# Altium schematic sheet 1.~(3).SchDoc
size 420 x 297 mm
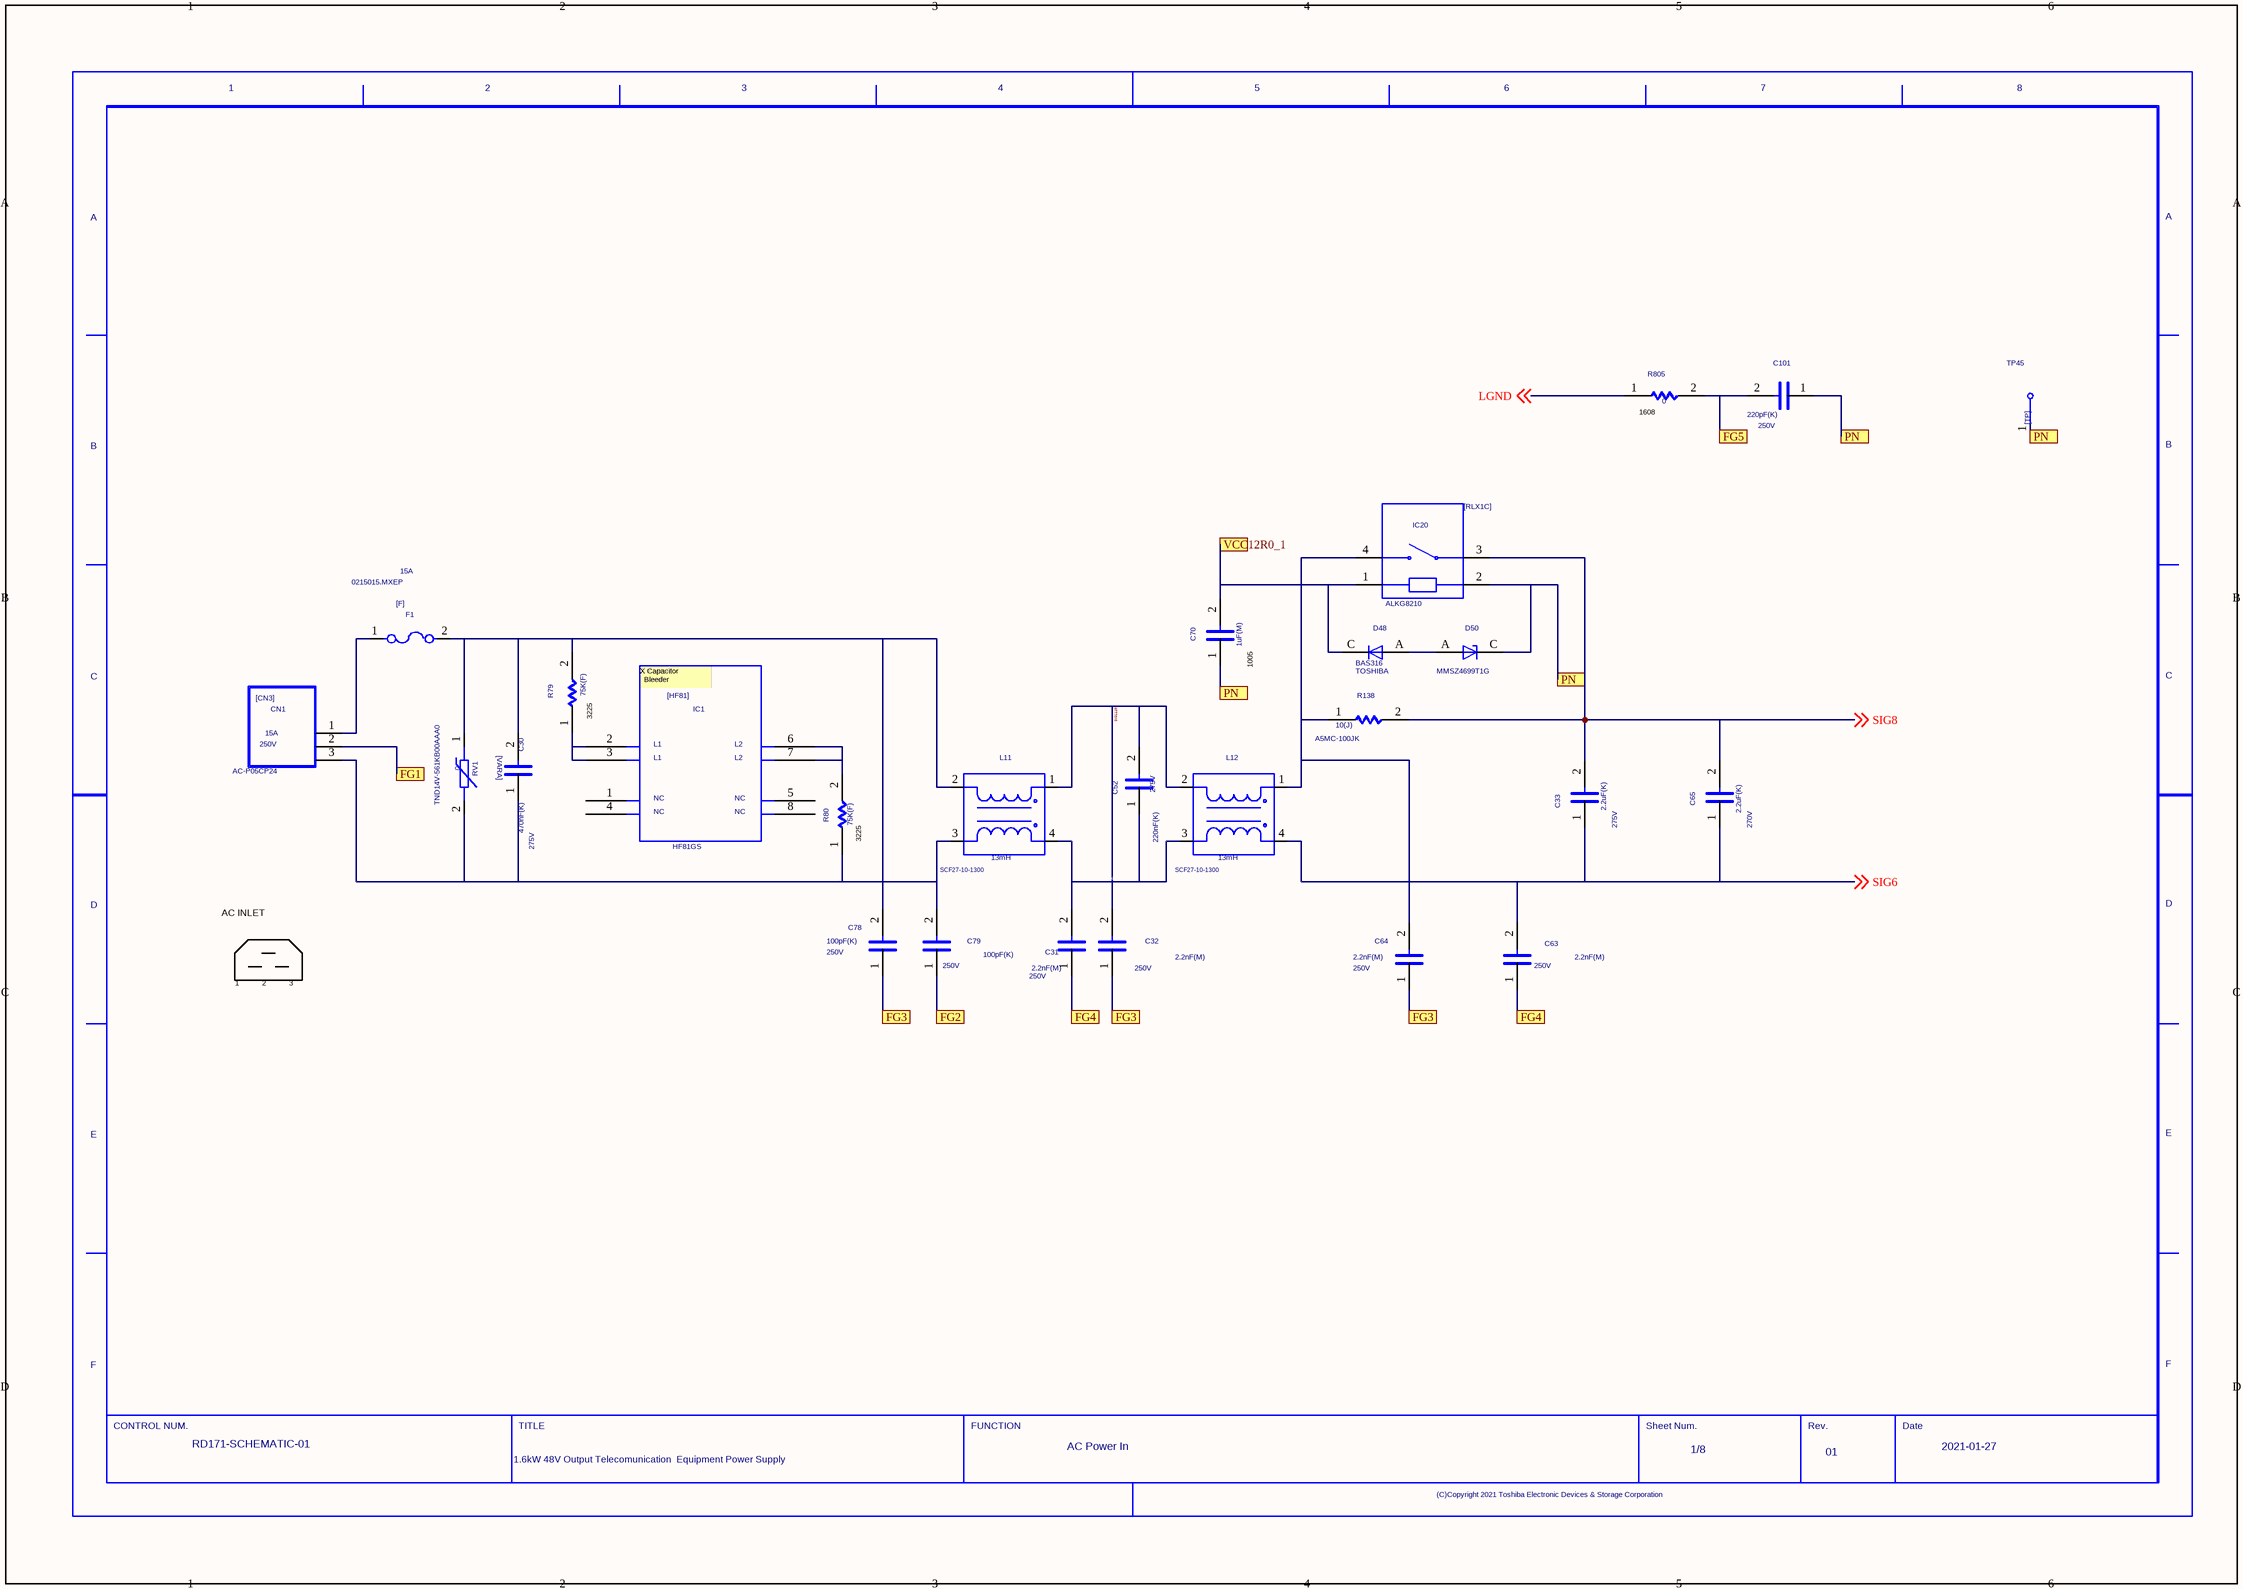
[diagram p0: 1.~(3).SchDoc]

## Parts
C30  VAL2: 275V  VAL1: 470nF(K)  [LE474-M]  (hidden comment: 470nF)
C31  VAL2: 250V  VAL1: 2.2nF(M)  [DE2E3KY222MN3AM02F]  (hidden comment: 2.2nF)
C32  VAL2: 250V  VAL1: 2.2nF(M)  [DE2E3KY222MN3AM02F]  (hidden comment: 2.2nF)
C33  VAL2: 275V  VAL1: 2.2uF(K)  [890324026034CS]  (hidden comment: 2.2uF)
C52  VAL2: 275V  VAL1: 220nF(K)  [LE224-M]  (hidden comment: 220nF)
C63  VAL2: 250V  VAL1: 2.2nF(M)  [DE2E3KY222MN3AM02F]  (hidden comment: 2.2nF)
C64  VAL2: 250V  VAL1: 2.2nF(M)  [DE2E3KY222MN3AM02F]  (hidden comment: 2.2nF)
C65  VAL2: 270V  VAL1: 2.2uF(K)  [890324026034CS]  (hidden comment: 2.2uF)
C70  VAL1: 1uF(M)  (hidden comment: 1uF)
C78  VAL2: 250V  VAL1: 100pF(K)  [DE2B3KY101KA3BM02F]  (hidden comment: 100pF)
C79  VAL2: 250V  VAL1: 100pF(K)  [DE2B3KY101KA3BM02F]  (hidden comment: 100pF)
C101  VAL2: 250V  VAL1: 220pF(K)  [DE2B3KY221KA3BM02F]  (hidden comment: 220pF)
CN1  VAL2: 250V  [AC-P05CP24]  (hidden comment: 15A)
D48  USERCOMPTEXT3: TOSHIBA  [BAS316]  (hidden comment: D48)
D50  D50  [MMSZ4699T1G]  (value not drawn)
F1  VAL1: 15A  [0215015.MXEP]  (hidden comment: 15 A)
IC1  IC1  [HF81GS]  (value not drawn)
IC20  IC20  [ALKG8210]  (value not drawn)
L11  13mH  [SCF27-10-1300]
L12  13mH  [SCF27-10-1300]
R79  VAL1: 75K(F)  (hidden comment: 75k)
R80  VAL1: 75K(F)  (hidden comment: 75k)
R138  VAL1: 10(J)  [A5MC-100JK]  (hidden comment: 10_2.1W- FUSE)
R805  0
RV1  560V  [TND14V-561KB00AAA0]  (value not drawn)
TP45  TP45  [LC-22-S-WHITE]  (value not drawn)
U?  DATE: 2021-01-27  REVISION: 01  SHEETNUMBER: 1/8  FUNCTION: AC Power In  TITLE: 1.6kW 48V Output Telecomunication / Equipment Power Supply  DRAWINGNUMBER: RD171-SCHEMATIC-01  (hidden comment: WAKU_DEF100)

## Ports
FG1, FG2, FG3, FG4, FG5, PN, VCC12R0_1

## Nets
FG1: CN1.2 ; port FG1
FG2: C79.1 ; port FG2
FG3: C32.1 C64.1 C78.1 ; port FG3
FG4: C31.1 C63.1 ; port FG4
FG5: C101.2 R805.2 ; port FG5
LGND: R805.1 ; off-sheet LGND
SIG1: C30.2 C78.2 F1.2 L11.2 R79.2 RV1.1
SIG2: C30.1 C79.2 CN1.3 L11.3 R80.1 RV1.2
SIG6: C33.1 C63.2 C65.1 L12.4 ; off-sheet SIG6
SIG8: C33.2 C65.2 C70.1 C101.1 D50.C IC20.2 IC20.3 R138.2 TP45.1 ; off-sheet SIG8, port PN
SIG9: IC1.2 IC1.3 R79.1
SIG10: IC1.6 IC1.7 R80.2
SIG193: CN1.1 F1.1
SIG200: C31.2 C52.1 L11.4 L12.3
SIG1119: C32.2 C52.2 L11.1 L12.2
SIGN275: D48.A D50.A
SIGN364: C64.2 IC20.4 L12.1 R138.1
VCC12R0_1: C70.2 D48.C IC20.1 ; port VCC12R0_1

Not connected (* = marked no-connect by the designer): IC1 1 4 5 8

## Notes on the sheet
- (near R805) 1608
- (near C70) 1005
- (near R79) 3225
- (near R80) 3225
- AC INLET
- 1
- 2
- 3

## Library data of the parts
C30 = C: PARTNAME: LE474-M_OK; ORIGINALSYMBOLORIGIN: (0,0); TIME: 16:40:04; UPDATEUSER: t5459927; SAVECOUNT: 1; COMPONENTNAME: C_C.Normal_package; SIZECODESMD: 3225; RATEDVOLTAGE: 100; ADSMODELNAME: s_GRM32MR72A474KA01L; CAPACITANCETOLE: K; NOMINALCAPACITA: 470n; MAKER: OKAYA; COMP: PRT_19; INSTANCENAME: INS121
C31 = C: PARTNAME: DE2E3KY222MN3AM02F_MU; ORIGINALSYMBOLORIGIN: (0,0); TIME: 16:40:04; UPDATEUSER: t5459927; SAVECOUNT: 1; QUADMODEL: CON_2.2N; FUNCTION: C_C.Normal_package; NOMINALCAPACITA: 2.2n; RATEDVOLTAGE: 250; CDMASTERCADCELG: DC0284; MAKER: MURATA; TEMPCHARACTERI2: E; SIZECODESMD: DIP; OUMEMAKER: NAE パナソニックエレクトロニックデバイス; COMP: PRT_13; ADSMODELNAME: s_ECKNTS222ME; PMPRODUCTSTYPEG: ES; FNLEADFREETHET1GT2GMCTH1: N_N_N; CAPACITANCETOLE: M; OUMECLASSIFICATION: セラミックコンデンサ; OUMEMAKERKATAMEI: ECKNTS222ME; CHIPSIZE: リードピッチ7.5mm品希望; INSTANCENAME: INS259
C32 = C: PARTNAME: DE2E3KY222MN3AM02F_MU; ORIGINALSYMBOLORIGIN: (0,0); TIME: 16:40:04; UPDATEUSER: t5459927; SAVECOUNT: 1; QUADMODEL: CON_2.2N; FUNCTION: C_C.Normal_package; NOMINALCAPACITA: 2.2n; RATEDVOLTAGE: 250; CDMASTERCADCELG: DC0284; MAKER: MURATA; TEMPCHARACTERI2: E; SIZECODESMD: DIP; OUMEMAKER: NAE パナソニックエレクトロニックデバイス; ADSCNVFLAG: ON; COMP: PRT_13; ADSMODELNAME: s_ECKNTS222ME; PMPRODUCTSTYPEG: ES; FNLEADFREETHET1GT2GMCTH1: N_N_N; CAPACITANCETOLE: M; OUMECLASSIFICATION: セラミックコンデンサ; OUMEMAKERKATAMEI: ECKNTS222ME; CHIPSIZE: リードピッチ7.5mm品希望; INSTANCENAME: INS269
C33 = C: PARTNAME: 890324026034CS_WE; ORIGINALSYMBOLORIGIN: (0,0); TIME: 16:40:04; UPDATEUSER: t5459927; SAVECOUNT: 1; COMPONENTNAME: C_C.Normal_package; FNLEADFREETHET1GT2GMCTH1: 9_N_N; SIZECODESMD: DIP; RATEDVOLTAGE: 250; OUMEMAKER: CHM 日本ケミコン; CAPACITANCETOLE: K; NOMINALCAPACITA: 2.2u; OUMECLASSIFICATION: フィルャRンデンサ; MAKER: Wurth; OUMEMAKERKATAMEI: TACB2E225K; CDMASTERCADCELG: DC0511; QUADMODEL: CON_2.2U; COMP: PRT_18; INSTANCENAME: INS309
C52 = C: PARTNAME: LE224-M_OK; ORIGINALSYMBOLORIGIN: (0,0); TIME: 16:40:04; UPDATEUSER: t5459927; SAVECOUNT: 1; COMPONENTNAME: C_C.Normal_package; FNLEADFREETHET1GT2GMCTH1: N_N_N; SIZECODESMD: DIP; RATEDVOLTAGE: 275; OUMEMAKER: NIS ニッセイ電機; CAPACITANCETOLE: M; NOMINALCAPACITA: 220n; OUMECLASSIFICATION: フィルャRンデンサ; MAKER: OKAYA; OUMEMAKERKATAMEI: R40KI322000**M; QUADMODEL: CON_220N; COMP: PRT_17; INSTANCENAME: INS279
C63 = C: PARTNAME: DE2E3KY222MN3AM02F_MU; ORIGINALSYMBOLORIGIN: (0,0); TIME: 16:40:04; UPDATEUSER: t5459927; SAVECOUNT: 1; QUADMODEL: CON_2.2N; FUNCTION: C_C.Normal_package; NOMINALCAPACITA: 2.2n; RATEDVOLTAGE: 250; CDMASTERCADCELG: SIK0018; MAKER: MURATA; TEMPCHARACTERI2: E; SIZECODESMD: DIP; OUMEMAKER: MRT 村田製作所; COMP: PRT_13; ADSMODELNAME: s_DE2E3KY222MN3AM02F; PMPRODUCTSTYPEG: PC1; FNLEADFREETHET1GT2GMCTH1: N_N_N; CAPACITANCETOLE: M; OUMECLASSIFICATION: セラミックコンデンサ; CHIPSIZE: リードピッチ7.5mm品希望; INSTANCENAME: INS289
C64 = C: PARTNAME: DE2E3KY222MN3AM02F_MU; ORIGINALSYMBOLORIGIN: (0,0); TIME: 16:40:04; UPDATEUSER: t5459927; SAVECOUNT: 1; QUADMODEL: CON_2.2N; FUNCTION: C_C.Normal_package; NOMINALCAPACITA: 2.2n; RATEDVOLTAGE: 250; CDMASTERCADCELG: SIK0018; MAKER: MURATA; TEMPCHARACTERI2: E; SIZECODESMD: DIP; OUMEMAKER: MRT 村田製作所; COMP: PRT_13; ADSMODELNAME: s_DE2E3KY222MN3AM02F; PMPRODUCTSTYPEG: PC1; FNLEADFREETHET1GT2GMCTH1: N_N_N; CAPACITANCETOLE: M; OUMECLASSIFICATION: セラミックコンデンサ; CHIPSIZE: リードピッチ7.5mm品希望; INSTANCENAME: INS299
C65 = C: PARTNAME: 890324026034CS_WE; ORIGINALSYMBOLORIGIN: (0,0); TIME: 16:40:04; UPDATEUSER: t5459927; SAVECOUNT: 1; COMPONENTNAME: C_C.Normal_package; FNLEADFREETHET1GT2GMCTH1: 9_N_N; SIZECODESMD: DIP; RATEDVOLTAGE: 250; OUMEMAKER: CHM 日本ケミコン; CAPACITANCETOLE: K; NOMINALCAPACITA: 2.2u; OUMECLASSIFICATION: フィルャRンデンサ; MAKER: Wurth; OUMEMAKERKATAMEI: TACB2E225K; CDMASTERCADCELG: DC0511; QUADMODEL: CON_2.2U; COMP: PRT_18; INSTANCENAME: INS319
C70 = C: PARTNAME: Chip1005_GS_2; ORIGINALSYMBOLORIGIN: (0,0); TIME: 16:40:04; UPDATEUSER: t5459927; SAVECOUNT: 1; QUADMODEL: CON_1U; FUNCTION: C_C.Normal_package; NOMINALCAPACITA: 1u; RATEDVOLTAGE: 25; CDMASTERCADCELG: KC0005; MAKER: TDK; TEMPCHARACTERI2: B; SIZECODESMD: 1005; OUMEMAKER: MRT 村田製作所; COMP: PRT_52; ADSMODELNAME: s_GRM155B31E105KA12D; PMPRODUCTSTYPEG: HD1; FNLEADFREETHET1GT2GMCTH1: 3_0_N; VAL3: C1005X5R1E105M050BC; VAL2: 25V; CAPACITANCETOLE: K; OUMECLASSIFICATION: セラミックコンデンサ; OUMEMAKERKATAMEI: GRM155B31E105KA12D; INSTANCENAME: INS339
C78 = C: PARTNAME: DE2B3KY101KA3BM02F_MU; ORIGINALSYMBOLORIGIN: (0,0); TIME: 16:40:04; UPDATEUSER: t5459927; SAVECOUNT: 1; QUADMODEL: CON_100P; FUNCTION: C_C.Normal_package; NOMINALCAPACITA: 100p; RATEDVOLTAGE: 250; CDMASTERCADCELG: RDK0051; MAKER: MURATA; TEMPCHARACTERI2: B; OUMEMAKER: MRT 村田製作所; COMP: PRT_29; ADSMODELNAME: s_DE1B3KX101KA4BL01; FNLEADFREETHET1GT2GMCTH1: N_N_N; CAPACITANCETOLE: K; OUMECLASSIFICATION: セラミックコンデンサ; OUMEMAKERKATAMEI: DE1B3KX101KA4BL01; CHIPSIZE: リードピッチ7.5mm品希望; INSTANCENAME: INS239
C79 = C: PARTNAME: DE2B3KY101KA3BM02F_MU; ORIGINALSYMBOLORIGIN: (0,0); TIME: 16:40:04; UPDATEUSER: t5459927; SAVECOUNT: 1; QUADMODEL: CON_100P; FUNCTION: C_C.Normal_package; NOMINALCAPACITA: 100p; RATEDVOLTAGE: 250; CDMASTERCADCELG: RDK0051; MAKER: MURATA; TEMPCHARACTERI2: B; OUMEMAKER: MRT 村田製作所; COMP: PRT_29; ADSMODELNAME: s_DE1B3KX101KA4BL01; FNLEADFREETHET1GT2GMCTH1: N_N_N; CAPACITANCETOLE: K; OUMECLASSIFICATION: セラミックコンデンサ; OUMEMAKERKATAMEI: DE1B3KX101KA4BL01; CHIPSIZE: リードピッチ7.5mm品希望; INSTANCENAME: INS249
C101 = C: PARTNAME: DE2B3KY221KA3BM02F_MU; ORIGINALSYMBOLORIGIN: (0,0); TIME: 16:40:04; UPDATEUSER: t5459927; SAVECOUNT: 1; QUADMODEL: CON_220P; FUNCTION: C_C.Normal_package; NOMINALCAPACITA: 220p; RATEDVOLTAGE: 1K; CDMASTERCADCELG: RD0002; MAKER: MURATA; TEMPCHARACTERI2: B; SIZECODESMD: DIP; OUMEMAKER: MRT 村田製作所; COMP: PRT_50; ADSMODELNAME: s_DEBB33A221KC1B; FNLEADFREETHET1GT2GMCTH1: 9_1_N; CAPACITANCETOLE: K; OUMECLASSIFICATION: セラミックコンデンサ; OUMEMAKERKATAMEI: DEBB33A221KC1B; INSTANCENAME: INS329
CN1 = CN3: PARTNAME: AC-P05CP24_ED; ORIGINALSYMBOLORIGIN: (0,0); TIME: 16:40:05; UPDATEUSER: t5459927; SAVECOUNT: 1; COMP: PRT_61; FUNCTION: CN3_CN3.Normal_package; MAKER: ECHO ELECTRIC; INSTANCENAME: INS363
D48 = D: PARTNAME: BAS316_TS_B; UPDATEUSER: t5459927; UPDATETIME: 16:40:05; SAVECOUNT: 1; SAVEAREA0: -225,-91,12804,7836; ORIGINALSYMBOLORIGIN: (0,0); FUNCTION: D_D.Normal_package; CDMASTERCADCELG: D8101D; FORWARDVOLTAGEM: 0; OUMEMAKER: IFO インフィニオンテクノロジーズ; MOUNTINGFORMSMD: SMD; COMP: PRT_26; ADSMODELNAME: s_BAS16_02W; FNLEADFREETHET1GT2GMCTH1: N_N_N; OUMECLASSIFICATION: その他ダイオード; OUMEMAKERKATAMEI: BAS16-02W; INSTANCENAME: INS163
D50 = ZD: PARTNAME: MMSZ4***T*G_OS_A; OUMEPARTTYPE: D; UPDATEUSER: t5459927; UPDATETIME: 16:40:05; SAVECOUNT: 1; SAVEAREA0: -4630,-153,17114,13055; ORIGINALSYMBOLORIGIN: (0,0); FUNCTION: ZD_ZD.Normal_package; CDMASTERCADCELG: MMK0127; MAKER: ON Semiconductor; FORWARDVOLTAGEM: 0; OUMEMAKER: ONS オンセミコンダクター; MOUNTINGFORMSMD: SMD; COMP: PRT_47; ADSMODELNAME: s_MMSZ4681T1G; FNLEADFREETHET1GT2GMCTH1: N_N_N; ZENERVOLTAGEMAX: 2.52; ZENERVOLTAGEMIN: 2.28; OUMECLASSIFICATION: 定電圧ダイオード; OUMEMAKERKATAMEI: MMSZ4681T1G; INSTANCENAME: INS153
F1 = F: PARTNAME: 02150***XEP_LF; ORIGINALSYMBOLORIGIN: (0,0); TIME: 16:40:04; UPDATEUSER: t5459927; SAVECOUNT: 1; COMP: PRT_21; RATEDINTERRUPTI: 0; FUNCTION: F_F.Normal_package; MOUNTINGFORMSMD: SMD; MAKER: Littelfuse; INSTANCENAME: INS109
IC1 = L81: PARTNAME: HF81GS_MPS; UPDATEUSER: t5459927; UPDATETIME: 16:40:04; SAVECOUNT: 1; SAVEAREA0: -25132,-33687,51942,1841; ORIGINALSYMBOLORIGIN: (0,0); COMP: PRT_45; FUNCTION: L81_L81.Normal_package; MAKER: MPS; INSTANCENAME: INS131
IC20 = RLX1C: PARTNAME: ALKG*2**_PN; SAVEAREA0: -15461,-296,40419,28727; ORIGINALSYMBOLORIGIN: (0,0); SAVECOUNT: 1; TIME: 14:49:55; UPDATEUSER: cae; UPDATETIME: 11:13:08; COMP: PRT_1; FUNCTION: RLX1C_RLX1C.Normal_package; MAKER: PANASONIC; INSTANCENAME: INS349
L11 = HM_DLWHN6702: PARTNAME: SCF27-10-1300_TN; UPDATEUSER: t5459927; UPDATETIME: 16:40:05; DEVICENAME: DLW21HN670SQ2; SAVECOUNT: 1; SAVEAREA0: -21350,-26515,41553,39372; ORIGINALSYMBOLORIGIN: (0,0); VAL2: 10A; COMPONENTNAME: HM-DLWHN6702_HM-DLWHN6702.Normal_package; MAKER: NEC TOKIN; COMP: PRT_22; INSTANCENAME: INS175
L12 = HM_DLWHN6702: PARTNAME: SCF27-10-1300_TN; UPDATEUSER: t5459927; UPDATETIME: 16:40:05; DEVICENAME: DLW21HN670SQ2; SAVECOUNT: 1; SAVEAREA0: -21350,-26515,41553,39372; ORIGINALSYMBOLORIGIN: (0,0); VAL2: 10A; COMPONENTNAME: HM-DLWHN6702_HM-DLWHN6702.Normal_package; MAKER: NEC TOKIN; COMP: PRT_22; INSTANCENAME: INS191
R79 = R: PARTNAME: Chip3225_GS_1; ORIGINALSYMBOLORIGIN: (0,0); TIME: 16:40:04; UPDATEUSER: t5459927; SAVECOUNT: 1; QUADMODEL: RES_56K; FUNCTION: R_R.Normal_package; CDMASTERCADCELG: DR903A; MAKER: PANASONIC; RESISTANCETOLER: F; SIZECODESMD: 3225; OUMEMAKER: KOA コーア; POWERRATING: 250m; MOUNTINGFORMSMD: SMD; NOMINALRESISTAN: 56K; COMP: PRT_23; ADSMODELNAME: s_RK73H2ETE563F; FNLEADFREETHET1GT2GMCTH1: N_N_N; VAL3: ERJ-14NF7502U; VAL2: 500mW,±1%; OUMECLASSIFICATION: 表面実装用固定抵抗器; OUMEMAKERKATAMEI: RK73H2ETE563F; INSTANCENAME: INS219
R80 = R: PARTNAME: Chip3225_GS_1; ORIGINALSYMBOLORIGIN: (0,0); TIME: 16:40:04; UPDATEUSER: t5459927; SAVECOUNT: 1; QUADMODEL: RES_56K; FUNCTION: R_R.Normal_package; CDMASTERCADCELG: DR903A; MAKER: PANASONIC; RESISTANCETOLER: F; SIZECODESMD: 3225; OUMEMAKER: KOA コーア; POWERRATING: 250m; MOUNTINGFORMSMD: SMD; NOMINALRESISTAN: 56K; COMP: PRT_23; ADSMODELNAME: s_RK73H2ETE563F; FNLEADFREETHET1GT2GMCTH1: N_N_N; VAL3: ERJ-14NF7502U; VAL2: 500mW,±1%; OUMECLASSIFICATION: 表面実装用固定抵抗器; OUMEMAKERKATAMEI: RK73H2ETE563F; INSTANCENAME: INS229
R138 = R: PARTNAME: A5MC_UC; ORIGINALSYMBOLORIGIN: (0,0); TIME: 16:40:04; UPDATEUSER: t5459927; SAVECOUNT: 1; COMP: PRT_33; CHIPSIZE: 13x9xH25.5; FUNCTION: R_R.Normal_package; MAKER: TAKMAN; INSTANCENAME: INS207
R805 = R: PARTNAME: Chip1608_GS_1; ORIGINALSYMBOLORIGIN: (0,0); TIME: 16:40:04; UPDATEUSER: t5459927; SAVECOUNT: 1; QUADMODEL: RES_0; FUNCTION: R_R.Normal_package; CDMASTERCADCELG: KCK0203; MAKER: KOA; RESISTANCETOLER: X; SIZECODESMD: 1608; OUMEMAKER: KOA コーア; POWERRATING: 100m; MOUNTINGFORMSMD: SMD; COMP: PRT_8; ADSMODELNAME: s_RK73Z1JTTD; PMPRODUCTSTYPEG: DME-HD1-PC1; FNLEADFREETHET1GT2GMCTH1: 3_2_N; VAL3: RK73Z1JTTD; VAL2: 100mW; OUMECLASSIFICATION: 表面実装用固定抵抗器; INSTANCENAME: INS17025352
RV1 = VARA: PARTNAME: TND14V-561_CC; OUMEPARTTYPE: RV; UPDATEUSER: t5459927; UPDATETIME: 16:40:05; SAVECOUNT: 1; SAVEAREA0: -9950,-8554,25168,13619; ORIGINALSYMBOLORIGIN: (0,0); FUNCTION: VARA_VARA.Normal_package; RATEDVOLTAGE: 0; CDMASTERCADCELG: KC0008; MAKER: NIPPON CHEMICON; OUMEMAKER: TDK ＴＤＫ; MOUNTINGFORMSMD: SMD; COMP: PRT_37; FNLEADFREETHET1GT2GMCTH1: N_N_N; OUMECLASSIFICATION: バリスタ; OUMEMAKERKATAMEI: AVR-M1608C220KT6AB; INSTANCENAME: INS99
TP45 = TP: PARTNAME: LC-22_GS; UPDATEUSER: t5459927; UPDATETIME: 16:40:05; SAVECOUNT: 1; SAVEAREA0: -242,-92,12810,7836; ORIGINALSYMBOLORIGIN: (0,0); COMP: PRT_49; FUNCTION: TP_TP.Normal_package; MAKER: MAC8; INSTANCENAME: INS379
U? = WAKU_DEF100: PLOTTIME: HH:MM; SAVEAREA0: 168739,-66042,466246,90057; TIME: 14:30:25; UPDATEUSER: t5459927; UPDATETIME: 15:16:57; SAVECOUNT: 5; OriginalSymbolOrigin: (10160,284480)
